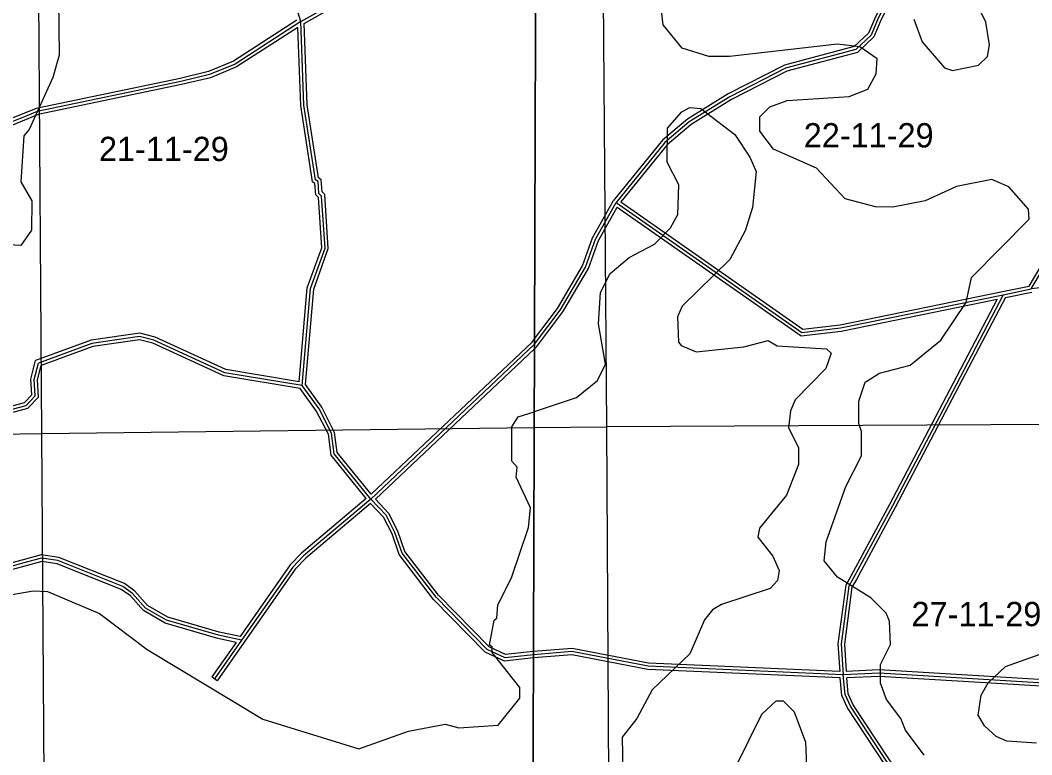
# Model space of a CAD drawing. Extents: x 457167 to 656239, y 1787309 to 1969297.
# Drawn here: x 532202 to 541585, y 1883975 to 1890789 of the extents above; entities that cross this region are included whole.
import ezdxf

# ---------------------------------------------------------------- set-up
doc = ezdxf.new("R2010")
doc.units = 0
for name, color, linetype in [('Level 1', 7, 'Continuous'), ('Level 2', 7, 'Continuous'), ('Level 31', 7, 'Continuous'), ('Level 32', 7, 'Continuous'), ('Level 63', 7, 'Continuous'), ('Level 7', 7, 'Continuous')]:
    doc.layers.add(name, color=color, linetype=linetype)

msp = doc.modelspace()

# ---------------------------------------------------------------- linework, layer by layer
at = {"layer": 'Level 1'}
for p, q in [((532401.835, 1886955.356), (532368.304, 1892221.06)), ((537599.773, 1892290.637), (537641.2, 1887017.605)), ((532401.835, 1886955.356), (536970.272, 1887009.634)), ((536970.272, 1887009.634), (537641.2, 1887017.605)), ((542947.277, 1887045.64), (537641.2, 1887017.605)), ((537641.2, 1887017.605), (537671.105, 1881768.851)), ((527117.747, 1886879.073), (532401.835, 1886955.356)), ((532441.272, 1881681.596), (532401.835, 1886955.356))]:
    msp.add_line(p, q, dxfattribs=at)
at = {"layer": 'Level 31'}
for p, q in [((541579.966, 1888296.373), (542283.339, 1889494.958)), ((541320.276, 1888242.994), (541579.966, 1888296.373)), ((534255.824, 1885037.468), (534005.277, 1884679.376))]:
    msp.add_line(p, q, dxfattribs=at)
for points in [[(534803.854, 1890776.16), (534738.123, 1891001.471), (534725.75, 1892177.175), (534769.472, 1892710.499), (534762.35, 1893060.713), (534688.274, 1893260.961), (534656.621, 1893694.528), (534534.326, 1894026.938)], [(534803.854, 1890776.16), (535054.599, 1890917.161), (536182.622, 1891604.783), (536884.93, 1893227.646)], [(540564.484, 1891780.686), (540438.255, 1891583.985), (540337.306, 1891234.111), (540312.131, 1891217.461), (540286.83, 1891058.992), (540161.068, 1890809.198), (540094.108, 1890651.222), (539951.852, 1890518.211), (539301.262, 1890344.978), (538783.628, 1890079.335), (538407.934, 1889847.066), (538182.478, 1889655.779), (537730.684, 1889098.661)], [(534803.854, 1890776.16), (534194.817, 1890382.876), (533957.88, 1890284.381), (533691.48, 1890220.895), (532359.918, 1889942.401), (532263.1, 1889901.632), (532108.015, 1889840.695), (531549.43, 1889805.112)], [(534816.355, 1887400.044), (534894.672, 1888300.171), (535029.473, 1888674.647), (534997.975, 1889158.398), (534972.931, 1889183.207), (534965.015, 1889291.6), (534940.264, 1889308.408), (534834.395, 1890000.77), (534803.854, 1890776.16)], [(536972.759, 1887783.667), (537211.308, 1888099.575), (537445.713, 1888499.196), (537538.135, 1888757.451), (537730.684, 1889098.661)], [(537730.684, 1889098.661), (539453.207, 1887893.541), (539811.775, 1887934.233), (541320.276, 1888242.994)], [(545794.878, 1888574.511), (544990.64, 1888285.633), (544791.701, 1888231.683), (544607.577, 1888133.689), (543417.895, 1888280.197), (542990.674, 1888251.315), (542695.042, 1888196.581), (542363.632, 1888297.961), (542190.975, 1888311.583), (542023.791, 1888346.279), (541579.966, 1888296.373)], [(541320.276, 1888242.994), (540882.278, 1887407.245), (540292.283, 1886282.879), (539931.74, 1885615.994), (539887.925, 1885539.039), (539816.907, 1885003.251), (539836.365, 1884716.276)], [(534816.355, 1887400.044), (534099.855, 1887519.488), (533442.486, 1887822.027), (533309.018, 1887855.925), (532867.03, 1887790.845), (532370.585, 1887609.221)], [(535454.445, 1886347.031), (536972.713, 1887783.606), (536972.759, 1887783.667)], [(534255.824, 1885037.468), (534041.595, 1885083.628), (533559.22, 1885223.404), (533363.659, 1885335.689), (533244.194, 1885470.996), (533153.76, 1885536.025), (532552.134, 1885775.848), (532399.86, 1885799.992), (532236.22, 1885753.992), (532127.662, 1885724.9), (532007.753, 1885725.665), (531292.625, 1886165.529), (531263.501, 1886206.718), (531293.009, 1886279.712), (531563.066, 1886665.358), (531748.565, 1887066.199), (531781.056, 1887080.999), (532023.974, 1887152.915), (532257.957, 1887216.497), (532340.308, 1887304.224), (532331.91, 1887456.619), (532370.585, 1887609.221)], [(535454.445, 1886347.031), (535114.21, 1886765.239), (535089.708, 1886956.959), (534974.036, 1887182.796), (534816.355, 1887400.044)], [(535454.445, 1886347.031), (534830.6, 1885821.782), (534730.701, 1885716.652), (534255.824, 1885037.468)], [(536963.505, 1884903.581), (536963.471, 1884903.578), (536699.378, 1884875.336), (536532.95, 1884950.782), (536059.317, 1885436.322), (535744.166, 1885846.079), (535678.313, 1886037.933), (535595.495, 1886196.751), (535454.445, 1886347.031)], [(539836.365, 1884716.276), (538027.723, 1884796.172), (537319.485, 1884931.527), (536963.505, 1884903.581)], [(543774.714, 1884171.041), (542770.497, 1884575.193), (540170.075, 1884731.959), (539836.365, 1884716.276)], [(540641.092, 1883180.28), (540624.544, 1883280.333), (540342.293, 1883756.131), (539902.248, 1884424.428), (539852.65, 1884532.949), (539836.365, 1884716.276)]]:
    msp.add_lwpolyline(points, dxfattribs=at)
at = {"layer": 'Level 32'}
for p, q in [((541560.85, 1888323.071), (542258.455, 1889511.827)), ((541314.236, 1888272.38), (541560.85, 1888323.071)), ((541340.248, 1888216.47), (541584.672, 1888266.711)), ((535496.77, 1886345.774), (536972.626, 1887742.223)), ((534205.348, 1885017.655), (533980.696, 1884696.574)), ((534280.405, 1885020.269), (534029.859, 1884662.176)), ((534029.859, 1884662.176), (533980.696, 1884696.574))]:
    msp.add_line(p, q, dxfattribs=at)
for points in [[(534834.555, 1890759.004), (535069.763, 1890891.271), (536206.371, 1891584.125), (536910.498, 1893211.187)], [(540525.94, 1891776.168), (540410.643, 1891596.506), (540311.544, 1891253.041), (540284.585, 1891235.212), (540257.94, 1891068.321), (540133.83, 1890821.811), (540068.97, 1890668.79), (539936.86, 1890545.265), (539290.43, 1890373.141), (538768.868, 1890105.481), (538390.242, 1889871.4), (538160.937, 1889676.846), (537705.796, 1889115.599)], [(540589.733, 1891764.483), (540465.866, 1891571.464), (540363.069, 1891215.181), (540339.677, 1891199.711), (540315.721, 1891049.662), (540188.306, 1890796.586), (540119.245, 1890633.655), (539966.845, 1890491.157), (539312.094, 1890316.816), (538798.388, 1890053.188), (538425.625, 1889822.732), (538204.019, 1889634.711), (537774.272, 1889104.779)], [(534768.79, 1890789.227), (534180.81, 1890409.542), (533948.585, 1890313.007), (533684.931, 1890250.175), (532350.943, 1889971.174), (532251.791, 1889929.422), (532101.418, 1889870.336), (531547.523, 1889835.052)], [(534775.947, 1890722.426), (534208.825, 1890356.21), (533967.175, 1890255.756), (533698.03, 1890191.615), (532368.893, 1889913.627), (532274.41, 1889873.843), (532114.612, 1889811.054), (531551.337, 1889775.172)], [(534789.28, 1887434.971), (534865.123, 1888306.66), (534999.13, 1888678.931), (534968.777, 1889145.093), (534943.829, 1889169.807), (534936.152, 1889274.936), (534912.586, 1889290.94), (534804.484, 1889997.903), (534775.946, 1890722.426)], [(534847.215, 1887408.601), (534924.221, 1888293.682), (535059.816, 1888670.364), (535027.173, 1889171.702), (535002.033, 1889196.607), (534993.88, 1889308.263), (534967.942, 1889325.876), (534864.305, 1890003.636), (534834.555, 1890759.004)], [(536972.626, 1887742.223), (536995.148, 1887763.533), (537236.302, 1888082.89), (537473.012, 1888486.441), (537565.52, 1888744.934), (537740.569, 1889055.131)], [(536972.92, 1887833.665), (537186.314, 1888116.26), (537418.415, 1888511.951), (537510.75, 1888769.967), (537705.795, 1889115.599)], [(537740.569, 1889055.131), (539445.311, 1887862.451), (539816.484, 1887904.574), (541264.36, 1888200.926)], [(537774.272, 1889104.779), (539461.104, 1887924.63), (539807.066, 1887963.892), (541314.26, 1888272.386)], [(541264.36, 1888200.925), (540855.71, 1887421.178), (540265.804, 1886296.983), (539905.506, 1885630.551), (539858.954, 1885548.791), (539786.773, 1885004.217), (539804.165, 1884747.727)], [(541340.248, 1888216.47), (540908.847, 1887393.311), (540318.762, 1886268.775), (539957.975, 1885601.436), (539916.895, 1885529.287), (539847.042, 1885002.285), (539864.31, 1884747.621)], [(534789.281, 1887434.971), (534108.75, 1887548.42), (533452.534, 1887850.429), (533310.585, 1887886.48), (532859.615, 1887820.076), (532345.399, 1887631.951)], [(534799.296, 1887372.472), (534090.96, 1887490.556), (533432.44, 1887793.626), (533307.45, 1887825.37), (532874.447, 1887761.612), (532395.775, 1887586.49)], [(535457.314, 1886391.045), (536950.278, 1887803.68), (536972.92, 1887833.665)], [(534205.348, 1885017.655), (534034.251, 1885054.521), (533547.408, 1885195.591), (533344.439, 1885312.131), (533223.939, 1885448.61), (533139.233, 1885509.519), (532544.133, 1885746.741), (532401.652, 1885769.332), (532244.163, 1885725.061), (532131.519, 1885694.874), (531999.177, 1885695.718), (531271.675, 1886143.193), (531229.549, 1886202.775), (531266.475, 1886294.123), (531536.96, 1886680.381), (531726.01, 1887088.891), (531770.529, 1887109.171), (532015.78, 1887181.776), (532241.895, 1887243.221), (532309.646, 1887315.395), (532301.703, 1887459.546), (532345.399, 1887631.951)], [(534242.66, 1885070.994), (534048.937, 1885112.735), (533571.033, 1885251.216), (533382.88, 1885359.247), (533264.449, 1885493.383), (533168.286, 1885562.531), (532560.135, 1885804.954), (532398.068, 1885830.652), (532228.278, 1885782.923), (532123.806, 1885754.925), (532016.328, 1885755.611), (531313.575, 1886187.865), (531297.455, 1886210.662), (531319.542, 1886265.301), (531589.172, 1886650.336), (531771.121, 1887043.507), (531791.584, 1887052.827), (532032.167, 1887124.052), (532274.019, 1887189.773), (532370.97, 1887293.053), (532362.117, 1887453.691), (532395.775, 1887586.49)], [(535412.558, 1886350.981), (535085.535, 1886752.946), (535060.614, 1886947.952), (534948.392, 1887167.053), (534799.297, 1887372.471)], [(535457.313, 1886391.044), (535142.883, 1886777.532), (535118.801, 1886965.966), (534999.68, 1887198.54), (534847.214, 1887408.601)], [(535412.558, 1886350.981), (534810.001, 1885843.657), (534707.404, 1885735.687), (534242.659, 1885070.994)], [(536963.602, 1884933.681), (536960.701, 1884933.454), (536704.318, 1884906.036), (536550.48, 1884975.775), (536082.023, 1885456.009), (535770.945, 1885860.471), (535705.956, 1886049.806), (535620.19, 1886214.276), (535496.77, 1886345.775)], [(535452.025, 1886305.772), (534851.198, 1885799.907), (534753.999, 1885697.616), (534280.41, 1885020.277)], [(536963.408, 1884873.4), (536694.439, 1884844.636), (536515.42, 1884925.79), (536036.611, 1885416.635), (535717.388, 1885831.688), (535650.67, 1886026.061), (535570.8, 1886179.225), (535452.025, 1886305.773)], [(539804.165, 1884747.726), (538031.22, 1884826.048), (537321.156, 1884961.751), (536963.602, 1884933.681)], [(539808.806, 1884687.463), (538024.227, 1884766.296), (537317.814, 1884901.303), (536966.24, 1884873.702), (536963.408, 1884873.4)], [(543766.832, 1884206.551), (542777.172, 1884604.846), (540170.274, 1884762.002), (539864.31, 1884747.621)], [(540610.281, 1883182.719), (540595.865, 1883269.876), (540316.85, 1883740.219), (539875.922, 1884409.857), (539823.223, 1884525.163), (539808.807, 1884687.462)], [(543763.513, 1884143.21), (542763.823, 1884545.541), (540169.877, 1884701.916), (539869.016, 1884687.776)], [(540671.904, 1883177.839), (540653.223, 1883290.79), (540367.737, 1883772.042), (539928.574, 1884438.998), (539882.077, 1884540.735), (539869.016, 1884687.776)]]:
    msp.add_lwpolyline(points, dxfattribs=at)
at = {"layer": 'Level 63'}
for points in [[(497176.54, 1878534.741), (536942.563, 1878385.707), (537088.612, 1923840.983), (497371.386, 1923990.389), (497176.54, 1878534.741)], [(536942.563, 1878385.707), (576708.29, 1878279.4), (576805.546, 1923734.416), (537088.612, 1923840.983), (536942.563, 1878385.707)]]:
    msp.add_lwpolyline(points, dxfattribs=at)
at = {"layer": 'Level 7'}
for points in [[(532556.701, 1890981.873), (532563.38, 1890465.011), (532504.332, 1890256.765), (532286.056, 1889773.981), (532235.846, 1889715.789), (532209.463, 1889290.698), (532308.947, 1889115.306), (532308.062, 1888840.209), (532207.572, 1888698.814), (532040.88, 1888707.682)], [(540587.148, 1883970.177), (540412.831, 1884204.151), (540371.479, 1884312.652), (540238.684, 1884488.175), (540180.79, 1884638.388), (540181.378, 1884813.452), (540273.666, 1884996.557), (540266.013, 1885213.333), (540232.901, 1885288.464), (540091.636, 1885430.636), (539783.818, 1885623.356), (539659.263, 1885773.838), (539676.49, 1885948.833), (539861.555, 1886465.097), (540004.154, 1886748.076), (540004.9, 1886973.161), (539980.119, 1887048.253), (539980.775, 1887256.658), (540039.714, 1887431.562), (540173.355, 1887514.496), (540457.019, 1887588.611), (540741.21, 1887821.111), (540975.739, 1888170.492), (541026.506, 1888403.748), (541561.757, 1888943.908), (541553.715, 1889035.61), (541371.009, 1889244.602), (541212.815, 1889311.822), (540887.5, 1889246.176), (540595.307, 1889113.74), (540295.002, 1889056.335), (540136.61, 1889056.852), (539853.433, 1889132.771), (539587.554, 1889417.084), (539188.004, 1889593.423), (539063.479, 1889760.546), (539063.907, 1889893.929), (539155.897, 1889985.332), (539314.479, 1890043.196), (539889.819, 1890083.014), (540065.08, 1890149.147), (540140.56, 1890290.601), (540149.358, 1890432.326), (539991.323, 1890541.186), (539782.979, 1890566.884), (538782.263, 1890453.378), (538590.53, 1890453.996), (538340.674, 1890529.805), (538166.327, 1890747.108), (538141.973, 1890955.622)], [(540492.318, 1890798.008), (540566.693, 1890589.374), (540774.32, 1890346.931), (540849.282, 1890321.691), (540849.282, 1890321.691), (541091.166, 1890370.926), (541174.816, 1890454.029), (541191.815, 1890562.341), (541159.16, 1890770.876), (541117.739, 1890854.367)], [(536970.748, 1887157.87), (536971.043, 1887157.967), (537363.268, 1887290.106), (537555.529, 1887447.871), (537631.018, 1887597.666), (537565.53, 1887973.035), (537583.146, 1888264.741), (537675.405, 1888439.506), (537850.955, 1888589.002), (538084.768, 1888713.298), (538235.308, 1888862.864), (538302.387, 1888987.718), (538311.613, 1889262.784), (538203.928, 1889471.518), (538204.933, 1889788.296), (538338.773, 1889937.931), (538413.934, 1889979.382), (538513.965, 1889970.714), (538829.965, 1889727.952), (538970.991, 1889519.079), (539028.925, 1889385.506), (538994.539, 1889052.178), (538927.121, 1888835.632), (538784.563, 1888569.324), (538341.362, 1888137.278), (538299.353, 1888037.365), (538306.936, 1887803.92), (538331.848, 1887770.509), (538473.371, 1887711.7), (538915.358, 1887760.276), (539140.601, 1887817.911), (539223.804, 1887767.631), (539682.232, 1887741.146), (539723.784, 1887699.335), (539673.315, 1887557.781), (539388.935, 1887266.931), (539346.925, 1887167.017), (539329.758, 1887008.664), (539420.872, 1886824.971)], [(532055.433, 1885448.096), (532322.357, 1885497.26), (532455.71, 1885488.501), (532938.561, 1885286.892), (533379.345, 1884952.001), (534452.665, 1884306.668), (535343.735, 1884028.693), (535802.79, 1884193.952), (536144.775, 1884259.558), (536269.718, 1884225.789), (536636.584, 1884249.624), (536837.474, 1884499.093), (536837.802, 1884599.125), (536580.422, 1884925.06), (536580.581, 1884975.081), (536555.61, 1884991.821), (536598.038, 1885225.107), (536623.108, 1885241.718), (536631.836, 1885366.731), (536757.704, 1885616.428), (536917.56, 1886082.741), (536934.817, 1886266.076), (536802.36, 1886549.931), (536810.989, 1886641.633), (536761.166, 1886700.154), (536762.171, 1887016.901), (536820.821, 1887108.435), (536970.748, 1887157.87)], [(539420.872, 1886824.971), (539420.345, 1886666.576), (539311.097, 1886383.498), (539059.998, 1886075.868), (539043.059, 1885992.546), (539184.224, 1885817.023), (539242.147, 1885683.471), (539225.188, 1885591.809), (539158.228, 1885517.006), (538707.613, 1885368.396), (538624.092, 1885318.635), (538548.772, 1885227.201), (538414.375, 1884910.842), (538063.174, 1884578.5), (537920.605, 1884312.192), (537786.666, 1884137.556), (537793.404, 1883645.675)], [(541629.545, 1884083.553), (541354.51, 1884101.1), (541254.607, 1884143.11), (541146.564, 1884243.471), (541088.531, 1884343.712), (541114.129, 1884527.047), (541181.178, 1884643.521), (541340.059, 1884793.056), (541940.955, 1885007.869)], [(538844.529, 1883875.723), (539079.485, 1884350.147), (539213.256, 1884474.772), (539279.947, 1884474.573), (539379.65, 1884374.211), (539487.117, 1884090.416), (539510.227, 1883498.462)]]:
    msp.add_lwpolyline(points, dxfattribs=at)

# ---------------------------------------------------------------- texts
at = {"layer": 'Level 2'}
for s, p in [('22-11-29', (539469.863, 1889609.451)), ('21-11-29', (532932.59, 1889482.804)), ('27-11-29', (540469.197, 1885167.853))]:
    msp.add_text(s, height=225, dxfattribs=at).set_placement(p)

doc.saveas('drawing.dxf')
